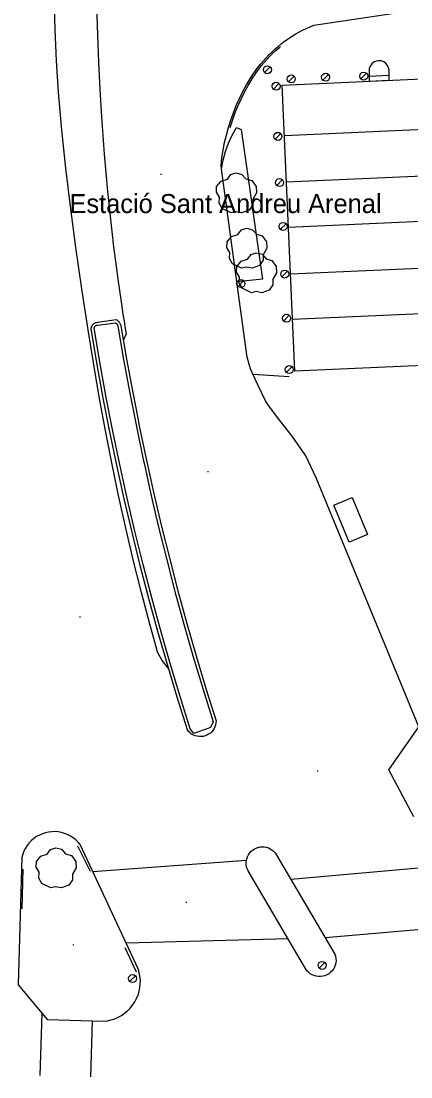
# Model space of a CAD drawing. Extents: x 431390 to 432653, y 4586754 to 4589600.
# Drawn here: x 431706 to 431745, y 4586837 to 4586942.6 of the extents above; entities that cross this region are included whole.
import ezdxf

# ---------------------------------------------------------------- set-up
doc = ezdxf.new("R2010")
doc.units = 0
for name, color, linetype in [('COM_02LS_LN', 7, 'Continuous'), ('COM_16_LN', 7, 'Continuous'), ('COM_17LS_LN', 7, 'Continuous'), ('COM_51_LN', 7, 'Continuous'), ('CON_01_LN', 7, 'Continuous'), ('CON_04_LN', 7, 'Continuous'), ('CON_09_LN', 7, 'Continuous'), ('CON_20_LN', 7, 'Continuous'), ('CON_29_LN', 7, 'Continuous'), ('ENE_06_PT', 7, 'Continuous'), ('HID_15_PT', 7, 'Continuous'), ('ORO_03_PT', 7, 'Continuous'), ('TOP_19_TX', 7, 'Continuous'), ('VEG_03_PT', 7, 'Continuous'), ('VEG_07LS_LN', 7, 'Continuous')]:
    doc.layers.add(name, color=color, linetype=linetype)

msp = doc.modelspace()

# ---------------------------------------------------------------- linework, layer by layer
at = {"layer": 'COM_02LS_LN'}
for points in [[(431720.76, 4586877.82), (431720.1, 4586878.66), (431719.65, 4586879.51), (431719.47, 4586880.15), (431719.16, 4586881.23), (431718.86, 4586882.31), (431718.03, 4586885.45), (431717.24, 4586888.61), (431716.5, 4586891.77), (431715.74, 4586895.17), (431715.03, 4586898.58), (431714.36, 4586902), (431713.78, 4586905.23), (431713.23, 4586908.47), (431712.71, 4586911.72), (431712.07, 4586915.83), (431711.47, 4586919.95), (431710.93, 4586924.07), (431710.48, 4586927.87), (431710.07, 4586931.67), (431709.75, 4586935.48), (431709.55, 4586938.6), (431709.41, 4586941.73), (431709.31, 4586944.86)], [(431713.53, 4586944.11), (431713.62, 4586941.22), (431713.73, 4586938.48), (431713.87, 4586935.75), (431714.04, 4586933.02), (431714.31, 4586929.29), (431714.63, 4586925.56), (431715.02, 4586921.84), (431715.28, 4586919.73)], [(431715.28, 4586919.73), (431715.33, 4586919.32), (431715.67, 4586916.8), (431716.03, 4586914.29), (431716.18, 4586913.28), (431716.32, 4586912.39)], [(431716.32, 4586912.39), (431716.34, 4586912.27), (431716.49, 4586911.26), (431716.48, 4586911.24)], [(431716.48, 4586911.24), (431716.22, 4586910.73)]]:
    msp.add_lwpolyline(points, dxfattribs=at)
at = {"layer": 'COM_16_LN'}
for points in [[(431713.32, 4586911.68), (431713.29, 4586911.85), (431713.3, 4586911.9), (431713.31, 4586911.94), (431713.33, 4586911.99), (431713.35, 4586912.02), (431713.38, 4586912.06), (431713.41, 4586912.09), (431713.45, 4586912.12), (431713.48, 4586912.14), (431713.53, 4586912.16), (431713.57, 4586912.17), (431713.62, 4586912.18), (431713.66, 4586912.18), (431715.42, 4586912.43), (431715.45, 4586912.41), (431715.48, 4586912.39), (431715.51, 4586912.37), (431715.53, 4586912.34), (431715.56, 4586912.31), (431715.58, 4586912.28), (431715.61, 4586912.25), (431715.63, 4586912.22), (431715.64, 4586912.18), (431715.66, 4586912.15), (431715.67, 4586912.11), (431715.68, 4586912.08), (431716.25, 4586908.74), (431716.86, 4586905.4), (431717.52, 4586902.07), (431718.21, 4586898.75), (431718.32, 4586898.27)], [(431724.76, 4586871.9), (431723.28, 4586871.38), (431722.91, 4586871.83), (431721.89, 4586875.08), (431720.91, 4586878.36), (431719.97, 4586881.65), (431719.07, 4586884.94), (431718.2, 4586888.26), (431717.38, 4586891.58), (431716.6, 4586894.91), (431715.86, 4586898.25), (431715.16, 4586901.6), (431714.51, 4586904.96), (431713.89, 4586908.32), (431713.32, 4586911.68)], [(431718.32, 4586898.27), (431718.94, 4586895.44), (431719.71, 4586892.14), (431720.53, 4586888.85), (431721.38, 4586885.56), (431722.28, 4586882.29), (431723.21, 4586879.03), (431724.19, 4586875.78), (431725.2, 4586872.55), (431724.95, 4586871.96), (431724.76, 4586871.9)]]:
    msp.add_lwpolyline(points, dxfattribs=at)
at = {"layer": 'COM_17LS_LN'}
for points in [[(431726.04, 4586927.81), (431726, 4586928.13), (431726.08, 4586928.9), (431726.2, 4586929.67), (431726.35, 4586930.43), (431726.52, 4586931.19), (431726.73, 4586931.94), (431726.96, 4586932.68), (431727.22, 4586933.41), (431727.51, 4586934.14), (431727.83, 4586934.84), (431728.18, 4586935.54), (431728.55, 4586936.22), (431728.95, 4586936.89), (431729.18, 4586937.24), (431729.41, 4586937.59), (431729.66, 4586937.93), (431729.92, 4586938.26), (431730.19, 4586938.58), (431730.47, 4586938.89), (431730.76, 4586939.2), (431731.06, 4586939.49), (431731.37, 4586939.77), (431731.69, 4586940.05), (431732.01, 4586940.31), (431732.35, 4586940.57), (431732.69, 4586940.81), (431733.04, 4586941.04), (431733.4, 4586941.26), (431733.76, 4586941.47), (431734.13, 4586941.66), (431734.51, 4586941.85), (431734.89, 4586942.02), (431735.28, 4586942.18), (431758.54, 4586945.67)], [(431745.27, 4586863.05), (431742.76, 4586867.75), (431745.78, 4586872.04), (431735.5, 4586896.92), (431734.46, 4586899.11), (431733.09, 4586901.08), (431731.86, 4586902.65), (431730.83, 4586904.02), (431730.42, 4586904.63), (431729.66, 4586906.21), (431728.94, 4586907.81), (431728.6, 4586908.99), (431727.58, 4586916.53)], [(431724.92, 4586871.42), (431724.92, 4586871.41), (431724.75, 4586871.29), (431724.58, 4586871.2), (431724.39, 4586871.13), (431724.2, 4586871.08), (431724, 4586871.06), (431723.8, 4586871.06), (431723.6, 4586871.09), (431723.41, 4586871.14), (431723.22, 4586871.22), (431723.05, 4586871.32), (431722.89, 4586871.44), (431722.75, 4586871.58), (431722.63, 4586871.74), (431721.61, 4586874.99), (431720.62, 4586878.27), (431719.68, 4586881.56), (431718.78, 4586884.87), (431717.91, 4586888.18), (431717.09, 4586891.51), (431716.31, 4586894.84), (431715.57, 4586898.18), (431714.87, 4586901.54), (431714.21, 4586904.9), (431713.59, 4586908.27), (431713.02, 4586911.63), (431713.01, 4586911.71), (431713, 4586911.81), (431713.01, 4586911.9), (431713.03, 4586911.99), (431713.06, 4586912.07), (431713.1, 4586912.15), (431713.15, 4586912.23), (431713.21, 4586912.29), (431713.28, 4586912.35), (431713.36, 4586912.4), (431713.44, 4586912.44), (431713.53, 4586912.46), (431713.62, 4586912.48), (431715.5, 4586912.75), (431715.56, 4586912.71), (431715.61, 4586912.68), (431715.66, 4586912.63), (431715.71, 4586912.59), (431715.76, 4586912.54), (431715.8, 4586912.49), (431715.84, 4586912.43), (431715.88, 4586912.38), (431715.91, 4586912.32), (431715.94, 4586912.26), (431715.96, 4586912.19), (431715.98, 4586912.13)], [(431715.98, 4586912.13), (431716.55, 4586908.79), (431717.16, 4586905.46), (431717.66, 4586902.88)], [(431717.66, 4586902.88), (431717.81, 4586902.13), (431718.5, 4586898.82), (431719.23, 4586895.51), (431720.01, 4586892.21), (431720.82, 4586888.92), (431721.67, 4586885.64), (431722.57, 4586882.37), (431723.5, 4586879.12), (431724.48, 4586875.87), (431725.49, 4586872.64), (431725.48, 4586872.44), (431725.44, 4586872.24), (431725.38, 4586872.05), (431725.3, 4586871.87), (431725.19, 4586871.7), (431725.06, 4586871.55), (431724.92, 4586871.42)], [(431717.71, 4586847.86), (431711.91, 4586860.27), (431711.7, 4586860.52), (431711.46, 4586860.74), (431711.21, 4586860.94), (431710.94, 4586861.12), (431710.65, 4586861.27), (431710.35, 4586861.38), (431710.03, 4586861.47), (431709.71, 4586861.53), (431709.39, 4586861.56), (431709.07, 4586861.55), (431708.74, 4586861.51), (431708.43, 4586861.44), (431708.12, 4586861.34), (431707.82, 4586861.21), (431707.54, 4586861.06), (431707.27, 4586860.87), (431707.02, 4586860.66), (431706.8, 4586860.43), (431706.59, 4586860.17), (431706.42, 4586859.9), (431706.27, 4586859.61), (431706.15, 4586859.31), (431706.06, 4586859), (431705.71, 4586846.25), (431708.6, 4586842.78), (431714.24, 4586842.61), (431714.62, 4586842.66), (431714.99, 4586842.74), (431715.36, 4586842.86), (431715.7, 4586843.01), (431716.04, 4586843.2), (431716.35, 4586843.42), (431716.64, 4586843.66), (431716.91, 4586843.93), (431717.15, 4586844.23), (431717.36, 4586844.55), (431717.54, 4586844.89), (431717.69, 4586845.24), (431717.8, 4586845.6), (431717.87, 4586845.98), (431717.91, 4586846.36), (431717.92, 4586846.74), (431717.88, 4586847.12), (431717.81, 4586847.49), (431717.71, 4586847.86)], [(431736.65, 4586847.29), (431736.58, 4586847.25), (431736.38, 4586847.16), (431736.16, 4586847.1), (431735.95, 4586847.08), (431735.73, 4586847.08), (431735.51, 4586847.11), (431735.3, 4586847.17), (431735.09, 4586847.25), (431734.9, 4586847.36), (431734.73, 4586847.5), (431734.58, 4586847.66), (431728.71, 4586857.63), (431728.62, 4586857.82), (431728.55, 4586858.02), (431728.51, 4586858.22), (431728.5, 4586858.43), (431728.52, 4586858.64), (431728.56, 4586858.85), (431728.63, 4586859.05), (431728.72, 4586859.23), (431728.84, 4586859.41), (431728.97, 4586859.57), (431729.13, 4586859.7), (431729.3, 4586859.82), (431729.49, 4586859.92), (431729.65, 4586859.97)], [(431729.65, 4586859.97), (431729.69, 4586859.99), (431729.89, 4586860.03), (431730.1, 4586860.05), (431730.31, 4586860.04), (431730.52, 4586860), (431730.72, 4586859.94), (431730.91, 4586859.85), (431731.08, 4586859.74), (431731.25, 4586859.6), (431731.39, 4586859.45), (431731.51, 4586859.28)], [(431731.51, 4586859.28), (431737.38, 4586849.31), (431737.44, 4586849.1), (431737.48, 4586848.88), (431737.49, 4586848.66), (431737.46, 4586848.44), (431737.41, 4586848.23), (431737.33, 4586848.02), (431737.23, 4586847.83), (431737.1, 4586847.65), (431736.94, 4586847.5), (431736.77, 4586847.36), (431736.65, 4586847.29)]]:
    msp.add_lwpolyline(points, dxfattribs=at)
at = {"layer": 'COM_51_LN'}
for points in [[(431713.16, 4586857.59), (431728.53, 4586858.71)], [(431732.97, 4586856.8), (431748.02, 4586858.14)], [(431751.47, 4586852.24), (431736.42, 4586850.94)], [(431732.7, 4586850.86), (431716.52, 4586850.4)], [(431707.91, 4586837.2), (431708.1, 4586843.38)], [(431712.96, 4586837.05), (431713.12, 4586842.65)]]:
    msp.add_lwpolyline(points, dxfattribs=at)
at = {"layer": 'CON_01_LN'}
msp.add_lwpolyline([(431732.1, 4586936.19), (431760.83, 4586937.47), (431762.11, 4586908.86), (431733.38, 4586907.58), (431732.1, 4586936.19)], dxfattribs=at)
at = {"layer": 'CON_04_LN'}
for points in [[(431761.27, 4586927.76), (431732.54, 4586926.47)], [(431732.95, 4586917.31), (431761.68, 4586918.59)]]:
    msp.add_lwpolyline(points, dxfattribs=at)
at = {"layer": 'CON_09_LN'}
msp.add_lwpolyline([(431737.27, 4586894.21), (431739.12, 4586894.97), (431740.65, 4586891.27), (431738.8, 4586890.51), (431737.27, 4586894.21)], dxfattribs=at)
at = {"layer": 'CON_20_LN'}
for points in [[(431726.9, 4586931.93), (431727.12, 4586932.63), (431727.38, 4586933.35), (431727.67, 4586934.07), (431727.99, 4586934.77), (431728.33, 4586935.46), (431728.7, 4586936.14), (431729.1, 4586936.8), (431729.26, 4586937.06), (431729.32, 4586937.15), (431729.55, 4586937.49), (431729.8, 4586937.82), (431730.05, 4586938.15), (431730.32, 4586938.47), (431730.6, 4586938.77), (431730.88, 4586939.07), (431731.18, 4586939.36), (431731.48, 4586939.65), (431731.8, 4586939.92), (431731.93, 4586940.03)], [(431732.81, 4586907.03), (431729.19, 4586907.26)], [(431712.93, 4586857.59), (431711.68, 4586860.1)], [(431706.18, 4586857.81), (431706.07, 4586853.86)], [(431716.36, 4586849.99), (431717.5, 4586847.56)]]:
    msp.add_lwpolyline(points, dxfattribs=at)
at = {"layer": 'CON_29_LN'}
for points in [[(431761.06, 4586932.4), (431732.33, 4586931.12)], [(431761.47, 4586923.24), (431732.74, 4586921.95)], [(431761.88, 4586914.02), (431733.15, 4586912.74)]]:
    msp.add_lwpolyline(points, dxfattribs=at)
at = {"layer": 'ENE_06_PT'}
for p, q in [((431730.91, 4586938), (431730.35, 4586937.44)), ((431736.73, 4586937.25), (431736.16, 4586936.68)), ((431740.55, 4586937.37), (431739.98, 4586936.8)), ((431731.78, 4586936.35), (431731.22, 4586935.79)), ((431733.3, 4586937.09), (431732.73, 4586936.52)), ((431731.97, 4586931.34), (431731.4, 4586930.77)), ((431732.12, 4586926.72), (431731.56, 4586926.16)), ((431732.49, 4586922.33), (431731.92, 4586921.77)), ((431732.64, 4586917.58), (431732.07, 4586917.01)), ((431728.25, 4586916.62), (431727.69, 4586916.06)), ((431732.82, 4586913.17), (431732.25, 4586912.6)), ((431733.09, 4586908.04), (431732.52, 4586907.47)), ((431736.38, 4586848.47), (431735.82, 4586847.91)), ((431717.42, 4586847.16), (431716.86, 4586846.6))]:
    msp.add_line(p, q, dxfattribs=at)
for centre in [(431730.63, 4586937.72), (431733.01, 4586936.8), (431736.45, 4586936.97), (431740.26, 4586937.08), (431731.5, 4586936.07), (431731.68, 4586931.06), (431731.84, 4586926.44), (431732.2, 4586922.05), (431732.36, 4586917.29), (431727.97, 4586916.34), (431732.54, 4586912.88), (431732.81, 4586907.75), (431736.1, 4586848.19), (431717.14, 4586846.88)]:
    msp.add_circle(centre, 0.4, dxfattribs=at)
at = {"layer": 'HID_15_PT'}
msp.add_lwpolyline([(431740.81, 4586937.09), (431742.81, 4586937.16), (431742.79, 4586937.66), (431742.74, 4586937.91), (431742.64, 4586938.15), (431742.47, 4586938.35), (431742.26, 4586938.51), (431742.01, 4586938.6), (431741.75, 4586938.62), (431741.5, 4586938.58), (431741.26, 4586938.47), (431741.06, 4586938.3), (431740.9, 4586938.09), (431740.81, 4586937.85), (431740.79, 4586937.59), (431740.81, 4586937.09), (431740.82, 4586936.59), (431742.82, 4586936.66), (431742.81, 4586937.16)], dxfattribs=at)
at = {"layer": 'ORO_03_PT'}
for p, q in [((431719.95, 4586927.28), (431720.05, 4586927.28)), ((431724.65, 4586897.55), (431724.75, 4586897.55)), ((431711.83, 4586883.04), (431711.93, 4586883.04)), ((431735.59, 4586867.65), (431735.69, 4586867.65)), ((431722.46, 4586854.51), (431722.56, 4586854.51)), ((431711.17, 4586850.25), (431711.27, 4586850.25))]:
    msp.add_line(p, q, dxfattribs=at)
at = {"layer": 'VEG_03_PT'}
for points in [[(431727.01, 4586923.41), (431726.09, 4586923.85), (431725.8, 4586924.37), (431725.82, 4586924.98), (431725.54, 4586925.47), (431725.55, 4586926.04), (431725.99, 4586926.57), (431726.64, 4586926.77), (431726.98, 4586927.23), (431727.5, 4586927.4), (431728.08, 4586927.26), (431728.48, 4586926.8), (431729.06, 4586926.63), (431729.49, 4586926.04), (431729.54, 4586925.4), (431729.16, 4586924.76), (431729.16, 4586924.21), (431728.79, 4586923.67), (431728.05, 4586923.4), (431727.48, 4586923.52), (431727.01, 4586923.41)], [(431728.05, 4586917.88), (431727.13, 4586918.32), (431726.84, 4586918.84), (431726.86, 4586919.45), (431726.58, 4586919.94), (431726.59, 4586920.51), (431727.03, 4586921.04), (431727.68, 4586921.24), (431728.02, 4586921.7), (431728.54, 4586921.87), (431729.12, 4586921.73), (431729.52, 4586921.27), (431730.1, 4586921.1), (431730.53, 4586920.51), (431730.58, 4586919.87), (431730.2, 4586919.23), (431730.2, 4586918.68), (431729.83, 4586918.14), (431729.09, 4586917.87), (431728.52, 4586917.99), (431728.05, 4586917.88)], [(431729.02, 4586915.43), (431728.1, 4586915.87), (431727.81, 4586916.39), (431727.83, 4586917), (431727.55, 4586917.49), (431727.56, 4586918.06), (431728, 4586918.59), (431728.65, 4586918.79), (431728.99, 4586919.25), (431729.51, 4586919.42), (431730.09, 4586919.28), (431730.49, 4586918.82), (431731.07, 4586918.65), (431731.5, 4586918.06), (431731.55, 4586917.42), (431731.17, 4586916.78), (431731.17, 4586916.23), (431730.8, 4586915.69), (431730.06, 4586915.42), (431729.49, 4586915.54), (431729.02, 4586915.43)], [(431708.98, 4586855.95), (431708.06, 4586856.39), (431707.77, 4586856.91), (431707.79, 4586857.52), (431707.51, 4586858.01), (431707.52, 4586858.58), (431707.96, 4586859.11), (431708.61, 4586859.31), (431708.95, 4586859.77), (431709.47, 4586859.94), (431710.05, 4586859.8), (431710.45, 4586859.34), (431711.03, 4586859.17), (431711.46, 4586858.58), (431711.51, 4586857.94), (431711.13, 4586857.3), (431711.13, 4586856.75), (431710.76, 4586856.21), (431710.02, 4586855.94), (431709.45, 4586856.06), (431708.98, 4586855.95)]]:
    msp.add_lwpolyline(points, dxfattribs=at)
at = {"layer": 'VEG_07LS_LN'}
for points in [[(431726.04, 4586927.81), (431726.21, 4586928.68), (431726.44, 4586929.54), (431726.74, 4586930.37), (431727.1, 4586931.18), (431727.53, 4586931.96), (431728.01, 4586931.74), (431730.13, 4586916.77), (431727.58, 4586916.53)], [(431727.58, 4586916.53), (431726.04, 4586927.81)]]:
    msp.add_lwpolyline(points, dxfattribs=at)

# ---------------------------------------------------------------- texts
at = {"layer": 'TOP_19_TX'}
msp.add_text('Estació Sant Andreu Arenal', height=1.9, dxfattribs=at).set_placement((431710.83, 4586923.39))

doc.saveas('drawing.dxf')
